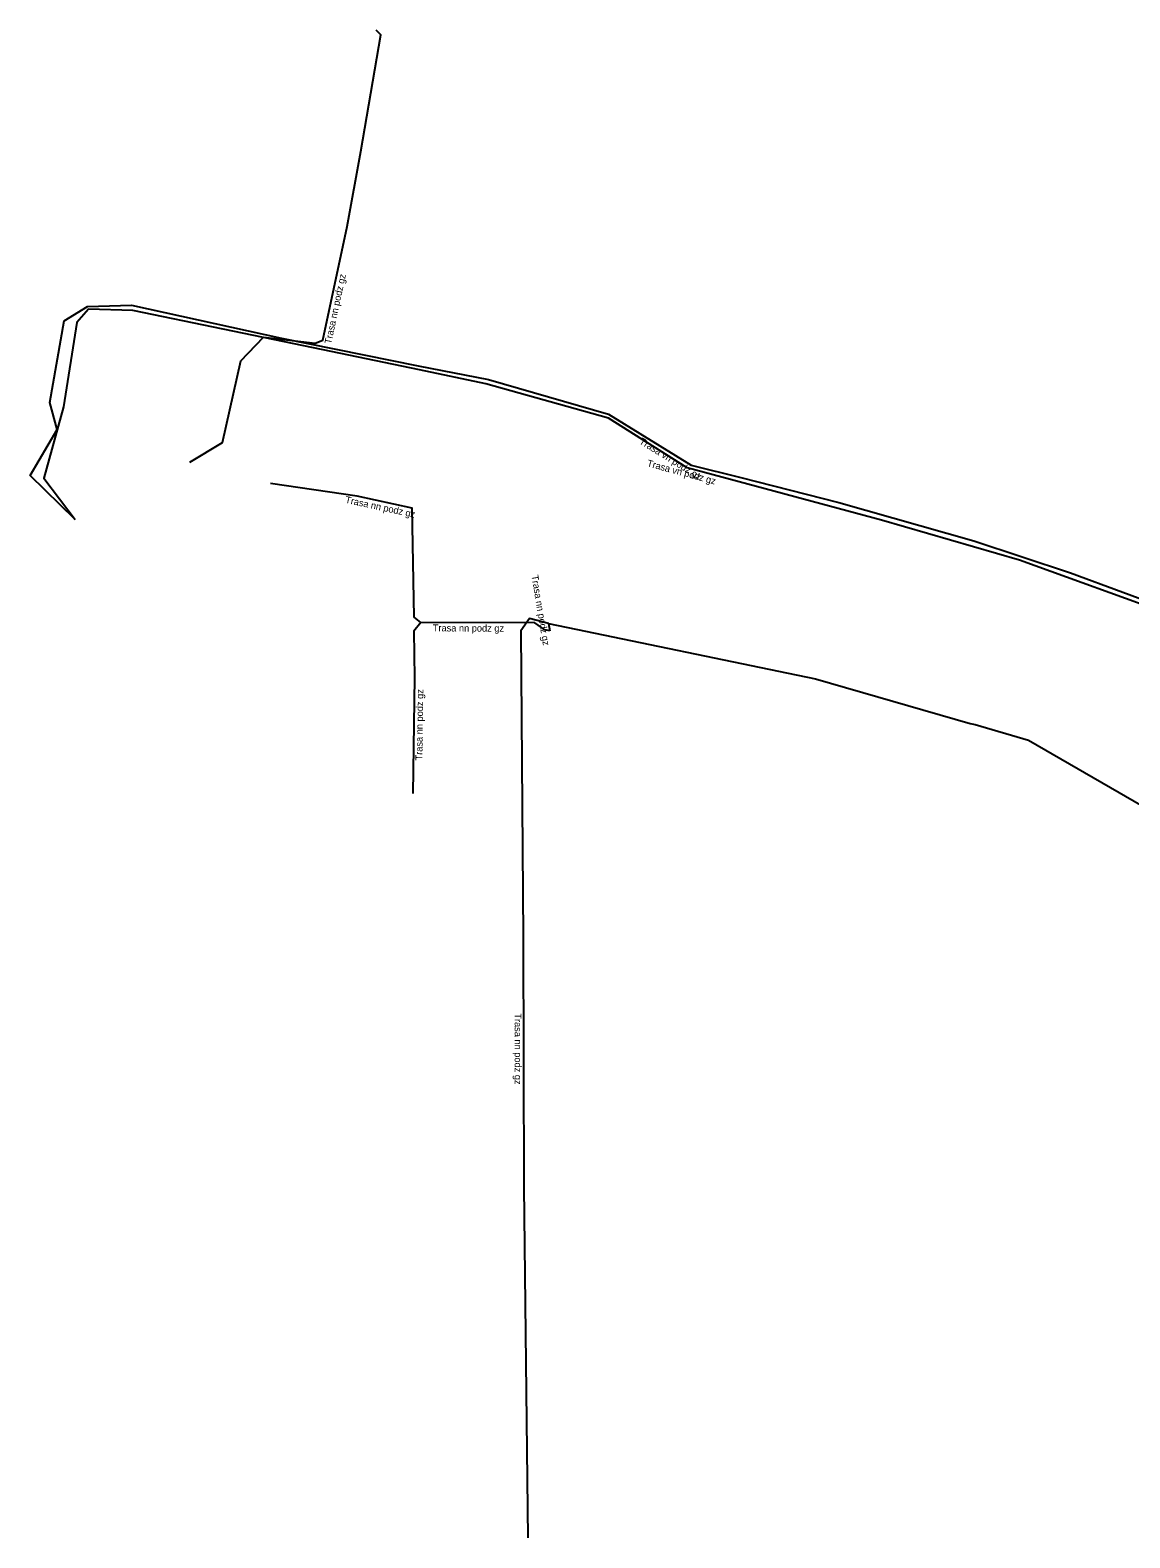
# Model space of a CAD drawing. Extents: x -725057 to -724754, y -1049160 to -1048651.
# Drawn here: x -725057.4 to -724977.7, y -1048930.4 to -1048821.1 of the extents above; entities that cross this region are included whole.
import ezdxf

# ---------------------------------------------------------------- set-up
doc = ezdxf.new("R2010")
doc.units = 0
for name, color, linetype in [('Popiskový text - Ostatní atributy Trasy', 7, 'Continuous'), ('Spojnice NN', 7, 'Continuous'), ('Spojnice VN', 7, 'Continuous')]:
    doc.layers.add(name, color=color, linetype=linetype)

msp = doc.modelspace()

# ---------------------------------------------------------------- linework, layer by layer
at = {"layer": 'Spojnice NN'}
for points in [[(-725045.85, -1048852.39), (-725043.49, -1048850.96), (-725042.16, -1048845.03), (-725040.51, -1048843.33), (-725036.78, -1048843.77), (-725036.21, -1048843.54), (-725034.46, -1048835.31), (-725033.47, -1048829.86), (-725032.01, -1048821.41), (-725032.35, -1048821.07)], [(-725029.1, -1048864), (-725029.58, -1048863.62), (-725029.73, -1048855.72), (-725033.73, -1048854.86), (-725040.02, -1048853.94)], [(-725019.85, -1048864.07), (-725021.22, -1048863.72), (-725021.86, -1048864.61), (-725021.68, -1048886.77), (-725021.63, -1048904.95), (-725021.34, -1048930.36)], [(-725029.1, -1048864), (-725029.62, -1048864.63), (-725029.56, -1048868.02), (-725029.68, -1048876.4)], [(-725019.76, -1048864.61), (-725020.12, -1048864.54), (-725020.83, -1048864.04), (-725029.1, -1048864)], [(-725019.85, -1048864.07), (-725000.49, -1048868.1), (-724989.28, -1048871.33), (-724988.91, -1048871.4), (-724985.03, -1048872.54), (-724971.44, -1048880.39), (-724951.69, -1048893.97), (-724936.92, -1048905.54), (-724935.69, -1048906.65), (-724934.98, -1048911.62), (-724934.42, -1048923.73)], [(-725019.85, -1048864.07), (-725019.76, -1048864.61)]]:
    msp.add_lwpolyline(points, dxfattribs=at)
at = {"layer": 'Spojnice VN'}
for points in [[(-725054.17, -1048856.55), (-725057.44, -1048853.35), (-725055.49, -1048850.01), (-725056, -1048848.07), (-725054.97, -1048842.15), (-725053.27, -1048841.1), (-725050.1, -1048841), (-725039.2, -1048843.4), (-725029.3, -1048845.4), (-725024.2, -1048846.4), (-725015.5, -1048848.9), (-725009.5, -1048852.6), (-725005.9, -1048853.5), (-724998.8, -1048855.3), (-724989, -1048858.1), (-724982, -1048860.4), (-724974.4, -1048863.2), (-724966.5, -1048867.3), (-724959.8, -1048870.7), (-724953.9, -1048874.6), (-724950.91, -1048876.65)], [(-724951, -1048876.88), (-724951.8, -1048876.3), (-724955.8, -1048873.7), (-724959.8, -1048871), (-724966.8, -1048867.5), (-724974.6, -1048863.5), (-724985.7, -1048859.5), (-724995.7, -1048856.6), (-725009.8, -1048852.8), (-725015.5, -1048849.2), (-725024.4, -1048846.7), (-725029.2, -1048845.7), (-725036.9, -1048844.1), (-725050, -1048841.4), (-725053.2, -1048841.3), (-725054.06, -1048842.26), (-725055.02, -1048848.37), (-725056.44, -1048853.55), (-725054.17, -1048856.55)]]:
    msp.add_lwpolyline(points, dxfattribs=at)

# ---------------------------------------------------------------- texts
at = {"layer": 'Popiskový text - Ostatní atributy Trasy'}
for s, rotation, p in [('Trasa nn podz gz', 77.9956, (-725035.61, -1048843.85)), ('Trasa vn podz gz', 328.3392, (-725013.31, -1048851.01)), ('Trasa vn podz gz', 344.9169, (-725012.74, -1048852.68)), ('Trasa nn podz gz', 347.8661, (-725034.62, -1048855.33)), ('Trasa nn podz gz', 279.4623, (-725021.09, -1048860.61)), ('Trasa nn podz gz', 359.7229, (-725028.24, -1048864.65)), ('Trasa nn podz gz', 89.1796, (-725029, -1048874.01)), ('Trasa nn podz gz', 270.1576, (-725022.31, -1048892.34))]:
    msp.add_text(s, height=0.5, rotation=rotation, dxfattribs=at).set_placement(p)

doc.saveas('drawing.dxf')
